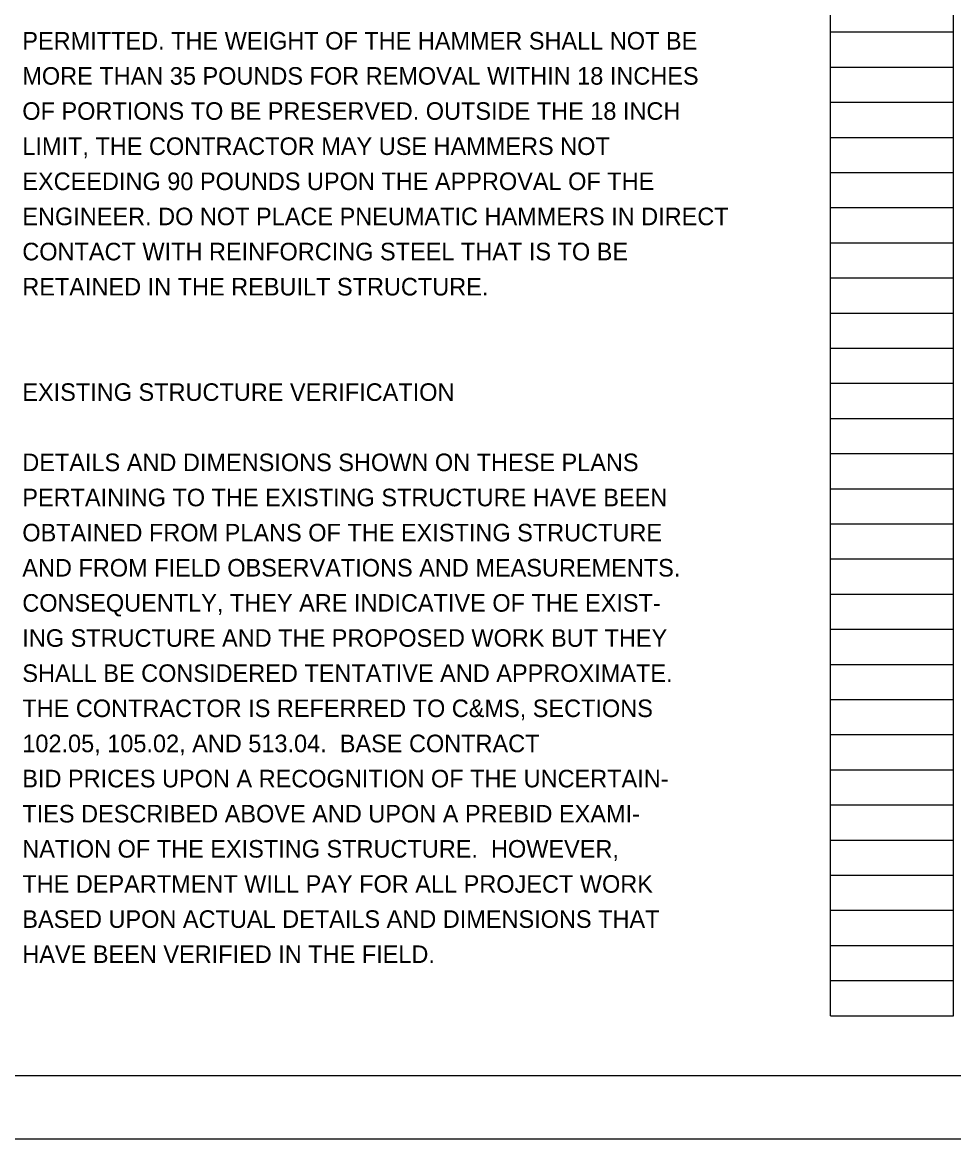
# Model space of a CAD drawing. Extents: x 0 to 34, y 0 to 22.
# Drawn here: x 17.24 to 24.66, y 0 to 8.9 of the extents above; entities that cross this region are included whole.
import ezdxf

# ---------------------------------------------------------------- set-up
doc = ezdxf.new("R2010")
doc.units = 0
for name, color, linetype in [('SH_Border', 7, 'Continuous'), ('SH_Cut_Line', 7, 'Continuous'), ('SH_Data', 7, 'Continuous'), ('SH_Text', 7, 'Continuous')]:
    doc.layers.add(name, color=color, linetype=linetype)

msp = doc.modelspace()

# ---------------------------------------------------------------- linework, layer by layer
at = {"layer": 'SH_Border'}
msp.add_lwpolyline([(1.5, 21.5), (33.5, 21.5), (33.5, 0.5), (1.5, 0.5)], close=True, dxfattribs=at)
at = {"layer": 'SH_Cut_Line'}
msp.add_lwpolyline([(0, 0), (34, 0), (34, 22), (0, 22)], close=True, dxfattribs=at)
at = {"layer": 'SH_Data'}
for p, q in [((23.68, 0.98), (23.68, 21.14)), ((24.66, 0.98), (24.66, 21.14)), ((23.68, 8.82), (24.66, 8.82)), ((23.68, 8.54), (24.66, 8.54)), ((23.68, 8.26), (24.66, 8.26)), ((23.68, 7.98), (24.66, 7.98)), ((23.68, 7.7), (24.66, 7.7)), ((23.68, 7.42), (24.66, 7.42)), ((23.68, 7.14), (24.66, 7.14)), ((23.68, 6.86), (24.66, 6.86)), ((23.68, 6.58), (24.66, 6.58)), ((23.68, 6.3), (24.66, 6.3)), ((23.68, 6.02), (24.66, 6.02)), ((23.68, 5.74), (24.66, 5.74)), ((23.68, 5.46), (24.66, 5.46)), ((23.68, 5.18), (24.66, 5.18)), ((23.68, 4.9), (24.66, 4.9)), ((23.68, 4.62), (24.66, 4.62)), ((23.68, 4.34), (24.66, 4.34)), ((23.68, 4.06), (24.66, 4.06)), ((23.68, 3.78), (24.66, 3.78)), ((23.68, 3.5), (24.66, 3.5)), ((23.68, 3.22), (24.66, 3.22)), ((23.68, 2.94), (24.66, 2.94)), ((23.68, 2.66), (24.66, 2.66)), ((23.68, 2.38), (24.66, 2.38)), ((23.68, 2.1), (24.66, 2.1)), ((23.68, 1.82), (24.66, 1.82)), ((23.68, 1.54), (24.66, 1.54)), ((23.68, 1.26), (24.66, 1.26)), ((23.68, 0.98), (24.66, 0.98))]:
    msp.add_line(p, q, dxfattribs=at)

# ---------------------------------------------------------------- texts
at = {"layer": 'SH_Text'}
for s, p in [('PERMITTED. THE WEIGHT OF THE HAMMER SHALL NOT BE', (17.24, 8.68)), ('MORE THAN 35 POUNDS FOR REMOVAL WITHIN 18 INCHES', (17.24, 8.4)), ('OF PORTIONS TO BE PRESERVED. OUTSIDE THE 18 INCH', (17.24, 8.12)), ('LIMIT, THE CONTRACTOR MAY USE HAMMERS NOT', (17.24, 7.84)), ('EXCEEDING 90 POUNDS UPON THE APPROVAL OF THE', (17.24, 7.56)), ('ENGINEER. DO NOT PLACE PNEUMATIC HAMMERS IN DIRECT', (17.24, 7.28)), ('CONTACT WITH REINFORCING STEEL THAT IS TO BE', (17.24, 7)), ('RETAINED IN THE REBUILT STRUCTURE.', (17.24, 6.72)), ('EXISTING STRUCTURE VERIFICATION', (17.24, 5.88)), ('DETAILS AND DIMENSIONS SHOWN ON THESE PLANS', (17.24, 5.32)), ('PERTAINING TO THE EXISTING STRUCTURE HAVE BEEN', (17.24, 5.04)), ('OBTAINED FROM PLANS OF THE EXISTING STRUCTURE', (17.24, 4.76)), ('AND FROM FIELD OBSERVATIONS AND MEASUREMENTS.', (17.24, 4.48)), ('CONSEQUENTLY, THEY ARE INDICATIVE OF THE EXIST-', (17.24, 4.2)), ('ING STRUCTURE AND THE PROPOSED WORK BUT THEY', (17.24, 3.92)), ('SHALL BE CONSIDERED TENTATIVE AND APPROXIMATE.', (17.24, 3.64)), ('THE CONTRACTOR IS REFERRED TO C&MS, SECTIONS', (17.24, 3.36)), ('102.05, 105.02, AND 513.04.  BASE CONTRACT', (17.24, 3.08)), ('BID PRICES UPON A RECOGNITION OF THE UNCERTAIN-', (17.24, 2.8)), ('TIES DESCRIBED ABOVE AND UPON A PREBID EXAMI-', (17.24, 2.52)), ('NATION OF THE EXISTING STRUCTURE.  HOWEVER,', (17.24, 2.24)), ('THE DEPARTMENT WILL PAY FOR ALL PROJECT WORK', (17.24, 1.96)), ('BASED UPON ACTUAL DETAILS AND DIMENSIONS THAT', (17.24, 1.68)), ('HAVE BEEN VERIFIED IN THE FIELD.', (17.24, 1.4))]:
    msp.add_text(s, height=0.14, dxfattribs=at).set_placement(p)

doc.saveas('drawing.dxf')
